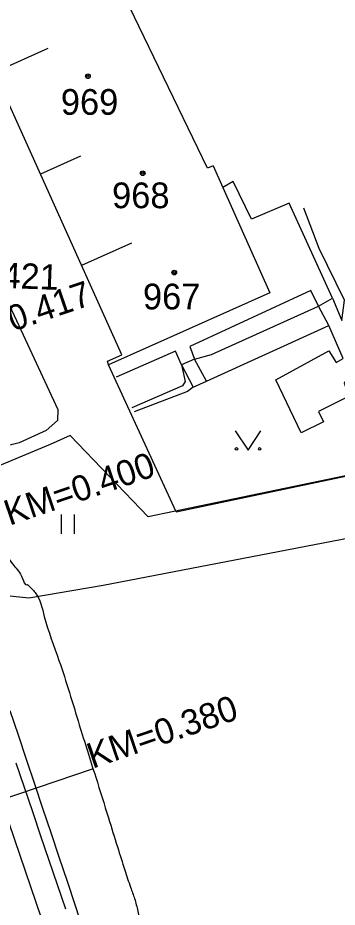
# Model space of a CAD drawing. Extents: x -478102 to -473059, y -1117705 to -1114104.
# Drawn here: x -476486.2 to -476461.4, y -1116879.8 to -1116810.6 of the extents above; entities that cross this region are included whole.
import ezdxf

# ---------------------------------------------------------------- set-up
doc = ezdxf.new("R2010")
doc.units = 0
for name, color, linetype in [('Budovy', 7, 'Continuous'), ('cesty', 7, 'Continuous'), ('LokalizacniPopisyPopisnaCisla', 7, 'Continuous'), ('ObPÚ', 7, 'Continuous'), ('OstatniRozhrani', 7, 'Continuous'), ('Ploty', 7, 'Continuous'), ('POLYGONY_SITUACE_PF', 7, 'Continuous'), ('POLYGONY_SITUACE_PF_POPISY', 7, 'Continuous'), ('POLYGONY_SITUACE_PO', 7, 'Continuous'), ('PopisnaZnackaVyhybka', 7, 'Continuous'), ('PopisneZnackyKultura', 7, 'Continuous'), ('RozhraniKultur', 7, 'Continuous'), ('RozhraniVozovky', 7, 'Continuous'), ('Teren_HranaSvahu', 7, 'Continuous'), ('Teren_PataSvahu', 7, 'Continuous'), ('Vrstevnice_hlavni', 7, 'Continuous'), ('Vrstevnice_vedlejsi', 7, 'Continuous'), ('Vrstva 36', 7, 'Continuous')]:
    doc.layers.add(name, color=color, linetype=linetype)

msp = doc.modelspace()

# ---------------------------------------------------------------- linework, layer by layer
at = {"layer": 'Budovy'}
for p, q in [((-476478.1, -1116836.8), (-476491.78, -1116806.38)), ((-476471.43, -1116822.291), (-476477.506, -1116809.723)), ((-476483.847, -1116812.976), (-476487.978, -1116814.834)), ((-476481.306, -1116821.349), (-476484.419, -1116822.749)), ((-476470.993, -1116822.098), (-476471.43, -1116822.291)), ((-476470.993, -1116822.098), (-476466.58, -1116831.98)), ((-476477.345, -1116828.114), (-476481.222, -1116829.858)), ((-476466.58, -1116831.98), (-476479.12, -1116837.58)), ((-476479.21, -1116837.29), (-476478.1, -1116836.8)), ((-476479.12, -1116837.58), (-476479.21, -1116837.29))]:
    msp.add_line(p, q, dxfattribs=at)
at = {"layer": 'cesty'}
for p, q in [((-476486.336, -1116868.552), (-476485.046, -1116872.338)), ((-476485.046, -1116872.338), (-476484.4, -1116874.231)), ((-476484.4, -1116874.231), (-476483.755, -1116876.124)), ((-476483.755, -1116876.124), (-476483.11, -1116878.017)), ((-476483.11, -1116878.017), (-476482.464, -1116879.91))]:
    msp.add_line(p, q, dxfattribs=at)
for points in [[(-476486.79, -1116864.481), (-476486.155, -1116866.377)], [(-476486.155, -1116866.377), (-476485.519, -1116868.273)], [(-476485.519, -1116868.273), (-476484.884, -1116870.17)], [(-476484.884, -1116870.17), (-476484.248, -1116872.066)], [(-476484.248, -1116872.066), (-476483.613, -1116873.963)], [(-476483.613, -1116873.963), (-476482.977, -1116875.859)], [(-476482.977, -1116875.859), (-476482.342, -1116877.755)], [(-476482.342, -1116877.755), (-476481.707, -1116879.652)], [(-476481.707, -1116879.652), (-476481.104, -1116881.559)]]:
    msp.add_lwpolyline(points, dxfattribs=at)
at = {"layer": 'ObPÚ'}
msp.add_lwpolyline([(-476357.4, -1116837.74), (-476422.93, -1116845.91), (-476427.37, -1116819.37), (-476430.29, -1116820.37), (-476436.91, -1116823.52), (-476455.71, -1116831.67), (-476450.1, -1116844.01), (-476476.04, -1116849.41), (-476482.1, -1116843.09), (-476483.67, -1116843.77), (-476488.84, -1116845.93), (-476490.13, -1116842.91), (-476508.98, -1116798.77)], dxfattribs=at)
at = {"layer": 'OstatniRozhrani'}
for points in [[(-476461.707, -1116832.388), (-476465.092, -1116824.994), (-476468.006, -1116826.249), (-476469.449, -1116823.315), (-476470.246, -1116823.772)], [(-476462.816, -1116833.026), (-476463.391, -1116831.793), (-476472.799, -1116836.158), (-476472.442, -1116837.139), (-476473.464, -1116837.594), (-476473.928, -1116836.511), (-476478.524, -1116838.533)], [(-476460.11, -1116838.658), (-476460.54, -1116838.607), (-476460.799, -1116839.008), (-476460.411, -1116840.025), (-476462.812, -1116841.214), (-476462.416, -1116842.015), (-476464.142, -1116842.86), (-476466.123, -1116838.743), (-476462.015, -1116836.504), (-476461.435, -1116837.392), (-476460.877, -1116837.079), (-476462.015, -1116834.526), (-476462.816, -1116833.026), (-476461.707, -1116832.388), (-476460.999, -1116834.138)], [(-476473.464, -1116837.594), (-476472.538, -1116839.319), (-476471.522, -1116838.85), (-476472.442, -1116837.139)]]:
    msp.add_lwpolyline(points, dxfattribs=at)
at = {"layer": 'Ploty'}
for points in [[(-476473.88, -1116849.03), (-476479.12, -1116837.58)], [(-476473.88, -1116849.03), (-476450.1, -1116844.01)]]:
    msp.add_lwpolyline(points, dxfattribs=at)
at = {"layer": 'POLYGONY_SITUACE_PF'}
msp.add_lwpolyline([(-476494.567, -1116873.851), (-476487.468, -1116871.431), (-476480.369, -1116869.011)], dxfattribs=at)
at = {"layer": 'POLYGONY_SITUACE_PO'}
msp.add_lwpolyline([(-476301.427, -1117045.065), (-476372.905, -1117052.019), (-476378.974, -1117051.908), (-476382.069, -1117051.436), (-476384.865, -1117050.444), (-476390.281, -1117047.7), (-476394.946, -1117043.817), (-476398.626, -1117038.989), (-476458.957, -1116938.029), (-476465.394, -1116926.586), (-476471.221, -1116914.82), (-476476.422, -1116902.765), (-476480.983, -1116890.454), (-476499.392, -1116836.452), (-476499.929, -1116834.228), (-476500.052, -1116831.944), (-476499.756, -1116829.676), (-476499.052, -1116827.5), (-476496.647, -1116821.88)], dxfattribs=at)
at = {"layer": 'PopisnaZnackaVyhybka'}
for centre, radius in [((-476480.728, -1116815.128), 0.18), ((-476480.728, -1116815.128), 0.0797), ((-476476.468, -1116822.675), 0.18), ((-476476.468, -1116822.675), 0.0797), ((-476474.014, -1116830.407), 0.18), ((-476474.014, -1116830.407), 0.0797)]:
    msp.add_circle(centre, radius, dxfattribs=at)
at = {"layer": 'PopisneZnackyKultura'}
for p, q in [((-476482.773, -1116850.729), (-476482.773, -1116849.229)), ((-476481.773, -1116850.729), (-476481.773, -1116849.229))]:
    msp.add_line(p, q, dxfattribs=at)
at = {"layer": 'RozhraniKultur'}
for p, q in [((-476454.277, -1116849.877), (-476479.541, -1116854.75)), ((-476479.541, -1116854.75), (-476485.323, -1116855.734)), ((-476485.323, -1116855.734), (-476488.011, -1116855.464))]:
    msp.add_line(p, q, dxfattribs=at)
at = {"layer": 'RozhraniVozovky'}
msp.add_lwpolyline([(-476490.349, -1116825.506), (-476486.291, -1116834.14), (-476483.076, -1116841.048), (-476483.085, -1116841.925), (-476483.97, -1116842.691), (-476486.077, -1116843.648), (-476487.217, -1116843.934), (-476487.93, -1116843.214), (-476491.436, -1116836.397), (-476497.994, -1116822.204), (-476502.044, -1116811.617), (-476503.151, -1116808.629), (-476503.828, -1116804.26), (-476503.771, -1116799.56), (-476501.723, -1116794.622), (-476498.437, -1116790.602), (-476493.387, -1116786.282), (-476488.978, -1116781.97)], dxfattribs=at)
at = {"layer": 'Teren_HranaSvahu'}
for points in [[(-476472.442, -1116837.139), (-476471.117, -1116836.787), (-476462.816, -1116833.026)], [(-476473.464, -1116837.594), (-476473.163, -1116838.875), (-476473.383, -1116839.212), (-476477.313, -1116840.929)]]:
    msp.add_lwpolyline(points, dxfattribs=at)
at = {"layer": 'Teren_PataSvahu'}
msp.add_line((-476471.522, -1116838.85), (-476462.015, -1116834.526), dxfattribs=at)
for points in [[(-476460.999, -1116834.138), (-476460.776, -1116832.542), (-476462.745, -1116828.534), (-476463.949, -1116825.387)], [(-476472.538, -1116839.319), (-476472.989, -1116839.652), (-476477.134, -1116841.25)]]:
    msp.add_lwpolyline(points, dxfattribs=at)
at = {"layer": 'Vrstevnice_hlavni'}
msp.add_spline([(-476493.715, -1116836.779), (-476493.657, -1116837.782), (-476493.454, -1116838.814), (-476493.106, -1116839.874), (-476492.613, -1116840.964), (-476491.914, -1116842.563), (-476491.008, -1116844.672), (-476489.895, -1116847.291), (-476489.121, -1116849.068), (-476488.687, -1116850.006), (-476488.591, -1116850.102), (-476488.194, -1116850.666), (-476487.494, -1116851.699), (-476486.491, -1116853.199), (-476485.812, -1116854.196), (-476485.456, -1116854.691), (-476485.422, -1116854.683), (-476485.307, -1116854.78), (-476485.109, -1116854.984), (-476484.829, -1116855.293), (-476484.118, -1116857.163), (-476482.975, -1116860.594), (-476481.402, -1116865.585), (-476480.12, -1116869.665), (-476479.13, -1116872.833), (-476478.431, -1116875.088), (-476477.86, -1116876.887), (-476477.416, -1116878.229), (-476477.099, -1116879.115), (-476476.855, -1116880.078), (-476476.685, -1116881.12), (-476476.587, -1116882.239), (-476476.21, -1116884.112), (-476475.555, -1116886.737), (-476474.62, -1116890.115), (-476473.657, -1116893.01), (-476472.666, -1116895.422), (-476471.647, -1116897.352), (-476470.243, -1116900.412), (-476468.455, -1116904.603), (-476466.283, -1116909.925), (-476464.77, -1116913.634), (-476463.916, -1116915.731), (-476463.721, -1116916.214), (-476463.617, -1116916.722), (-476463.603, -1116917.256), (-476463.679, -1116917.815), (-476463.509, -1116918.911), (-476463.093, -1116920.547), (-476462.43, -1116922.72), (-476462.028, -1116926.548), (-476461.886, -1116932.03), (-476462.123, -1116946.304)], degree=3, dxfattribs=at)
at = {"layer": 'Vrstevnice_vedlejsi'}
msp.add_spline([(-476452.85, -1116834.766), (-476452.763, -1116836.45), (-476452.562, -1116837.981), (-476452.248, -1116839.358), (-476451.821, -1116840.582), (-476451.441, -1116841.599), (-476451.108, -1116842.409), (-476450.824, -1116843.01), (-476450.631, -1116843.458), (-476450.53, -1116843.75), (-476450.521, -1116843.889), (-476450.642, -1116844.019), (-476450.893, -1116844.142), (-476451.274, -1116844.257), (-476451.636, -1116844.362), (-476451.98, -1116844.456), (-476452.305, -1116844.54), (-476452.489, -1116844.891), (-476452.534, -1116845.508), (-476452.439, -1116846.393), (-476452.377, -1116847.124), (-476452.349, -1116847.701), (-476452.354, -1116848.126), (-476452.334, -1116848.53), (-476452.288, -1116848.914), (-476452.216, -1116849.278), (-476451.375, -1116851.721), (-476449.763, -1116856.244), (-476447.382, -1116862.847), (-476445.375, -1116868.421), (-476443.743, -1116872.966), (-476442.485, -1116876.483), (-476441.641, -1116878.888), (-476441.211, -1116880.182), (-476441.195, -1116880.364), (-476441.153, -1116880.565), (-476441.084, -1116880.785), (-476440.99, -1116881.025), (-476440.244, -1116882.086), (-476438.849, -1116883.967), (-476436.803, -1116886.669), (-476434.982, -1116889.477), (-476433.386, -1116892.391), (-476432.015, -1116895.411), (-476430.876, -1116899.416), (-476429.969, -1116904.405), (-476429.293, -1116910.379), (-476428.831, -1116914.444), (-476428.585, -1116916.601), (-476428.553, -1116916.85), (-476428.523, -1116917.047), (-476428.494, -1116917.192), (-476428.467, -1116917.285), (-476428.451, -1116917.352), (-476428.447, -1116917.391), (-476428.453, -1116917.404), (-476428.455, -1116917.446), (-476428.452, -1116917.518), (-476428.446, -1116917.62), (-476428.12, -1116922.385), (-476427.475, -1116931.814), (-476426.511, -1116945.907), (-476425.976, -1116956.8), (-476425.87, -1116964.494), (-476426.194, -1116968.988), (-476426.432, -1116974.931), (-476426.584, -1116982.322), (-476426.65, -1116991.161), (-476427.252, -1117000.578), (-476428.388, -1117010.572), (-476430.059, -1117021.144), (-476430.881, -1117029.111), (-476430.854, -1117034.474), (-476429.978, -1117037.232), (-476429.977, -1117042.889), (-476430.852, -1117051.444), (-476432.602, -1117062.898), (-476433.9, -1117071.162), (-476434.745, -1117076.235), (-476435.138, -1117078.117), (-476435.697, -1117079.572), (-476436.421, -1117080.6), (-476437.311, -1117081.2), (-476438.104, -1117081.861), (-476438.8, -1117082.583), (-476439.4, -1117083.366), (-476442.225, -1117086.66), (-476447.274, -1117092.463), (-476454.548, -1117100.776), (-476460.096, -1117107.53), (-476463.917, -1117112.726), (-476466.012, -1117116.363), (-476467.87, -1117119.015), (-476469.493, -1117120.681), (-476470.879, -1117121.362), (-476472.889, -1117123.083), (-476475.524, -1117125.843)], degree=3, dxfattribs=at)
at = {"layer": 'Vrstva 36'}
msp.add_lwpolyline([(-476469.278, -1116842.726), (-476468.278, -1116844.226), (-476467.278, -1116842.726)], dxfattribs=at)
for centre in [(-476469.178, -1116844.126), (-476467.379, -1116844.126)]:
    msp.add_circle(centre, 0.1, dxfattribs=at)

# ---------------------------------------------------------------- texts
at = {"layer": 'LokalizacniPopisyPopisnaCisla'}
for s, p in [('969', (-476482.83, -1116818.126)), ('968', (-476478.849, -1116825.395)), ('967', (-476476.449, -1116833.267))]:
    msp.add_text(s, height=2, dxfattribs=at).set_placement(p)
at = {"layer": 'POLYGONY_SITUACE_PF_POPISY'}
for s, rotation, p in [('KM=0.421', 357.88167, (-476495.157, -1116831.306)), ('KM=0.417', 18.82411, (-476491.779, -1116836.784)), ('KM=0.400', 18.82411, (-476486.827, -1116850.104)), ('KM=0.380', 18.82411, (-476480.381, -1116869.015))]:
    msp.add_text(s, height=1.9765, rotation=rotation, dxfattribs=at).set_placement(p)

doc.saveas('drawing.dxf')
